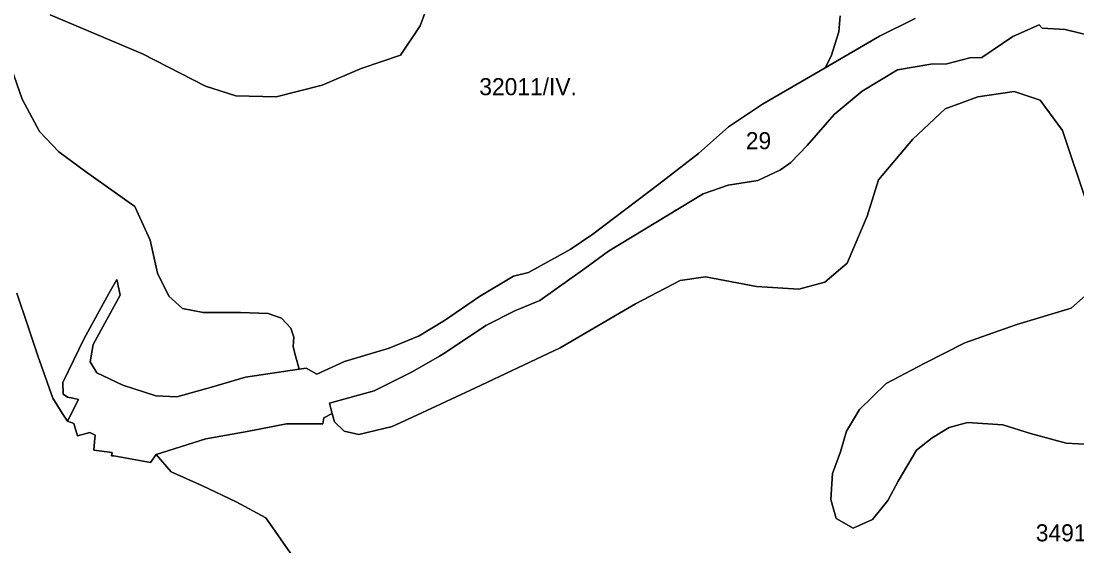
# Model space of a CAD drawing. Extents: x -521621 to -516761, y -1190184 to -1184927.
# Drawn here: x -518666 to -517738, y -1186934 to -1186473 of the extents above; entities that cross this region are included whole.
import ezdxf

# ---------------------------------------------------------------- set-up
doc = ezdxf.new("R2010")
doc.units = 0
doc.layers.add('BPEJ_s', color=7, linetype='Continuous')

msp = doc.modelspace()

# ---------------------------------------------------------------- linework, layer by layer
at = {"layer": 'BPEJ_s'}
for points in [[(-518640.68, -1186467.13), (-518559.44, -1186501.43), (-518504.22, -1186530.01), (-518477.56, -1186538.26), (-518442.01, -1186539.22), (-518401.39, -1186529.05), (-518367.11, -1186514.45), (-518332.52, -1186502.7), (-518315.38, -1186476.97), (-518305.23, -1186449.66)], [(-518305.23, -1186449.66), (-518315.38, -1186476.97), (-518332.52, -1186502.7), (-518367.11, -1186514.45), (-518401.39, -1186529.05), (-518442.01, -1186539.22), (-518477.56, -1186538.26), (-518504.22, -1186530.01), (-518559.44, -1186501.43), (-518640.68, -1186467.13)], [(-517945.65, -1186468.08), (-517946.92, -1186482.05), (-517953.58, -1186503.65), (-517958.84, -1186513.72), (-518014.04, -1186545.82), (-518044.12, -1186565.67), (-518070.38, -1186589.16), (-518105.19, -1186616.07), (-518163.5, -1186659.99), (-518183.31, -1186673.59), (-518220.01, -1186693.57), (-518233.13, -1186696.95), (-518262.99, -1186714.7), (-518293.79, -1186735.96), (-518316.22, -1186749.43), (-518342.54, -1186760.21), (-518381.71, -1186771.88), (-518406.33, -1186783.1), (-518415.68, -1186777.9), (-518421.78, -1186778.73), (-518425.83, -1186763.8), (-518427.02, -1186758.62), (-518426.5, -1186750.66), (-518429.2, -1186742.53), (-518437.32, -1186733.96), (-518449.05, -1186729.9), (-518473.4, -1186728.99), (-518506.33, -1186728.99), (-518524.37, -1186725.38), (-518536.54, -1186714.55), (-518546.47, -1186694.24), (-518552.78, -1186665.36), (-518566.31, -1186635.58), (-518609.61, -1186604.89), (-518633.07, -1186587.49), (-518650.2, -1186569.7), (-518665.44, -1186541.44), (-518677.5, -1186506.82)], [(-517879.79, -1186470.53), (-517911.12, -1186485.97), (-517958.84, -1186513.72), (-517953.58, -1186503.65), (-517946.92, -1186482.05), (-517945.65, -1186468.08)], [(-517720.36, -1186486.68), (-517747.87, -1186480.09), (-517768, -1186478.87), (-517770.79, -1186475.88), (-517793.73, -1186486.26), (-517821.06, -1186504.63), (-517831.83, -1186505.03), (-517851.97, -1186510.22), (-517865.93, -1186510.42), (-517895.2, -1186515.6), (-517926.37, -1186534.26), (-517951.06, -1186554.93), (-517974.73, -1186582.19), (-517989.16, -1186596.95), (-517998.24, -1186603.5), (-518018.2, -1186612.88), (-518044.36, -1186616.82), (-518066.39, -1186624.5), (-518149.53, -1186674.86), (-518170.5, -1186690.08), (-518209.87, -1186718.44), (-518231.94, -1186727.4), (-518257.59, -1186740.34), (-518292.98, -1186764.02), (-518298.35, -1186767.41), (-518322.21, -1186780.98), (-518355.75, -1186797.77), (-518394.91, -1186808.57), (-518393.36, -1186815.67), (-518392.84, -1186817.75), (-518400.1, -1186821.56), (-518400.97, -1186826.76), (-518432.75, -1186826.64), (-518467.55, -1186833.37), (-518503.82, -1186839.81), (-518547.6, -1186853.6), (-518552.44, -1186860.72), (-518584.71, -1186854.82), (-518586.88, -1186854.75), (-518586.36, -1186851.87), (-518602.52, -1186850.05), (-518601.71, -1186842.53), (-518601.12, -1186836.85), (-518606.01, -1186834.51), (-518616.73, -1186837.25), (-518620.06, -1186826.43), (-518625.42, -1186824.4), (-518615.73, -1186805.32), (-518620.98, -1186804.32), (-518625.56, -1186803.41), (-518629.47, -1186800.57), (-518629.72, -1186790.56), (-518610.91, -1186751.63), (-518589.12, -1186712.27), (-518582.06, -1186699.86), (-518579.29, -1186713.55), (-518603.01, -1186756.98), (-518605.57, -1186772.17), (-518599.8, -1186782.01), (-518576.96, -1186792.89), (-518547.69, -1186802.01), (-518529.34, -1186803.13), (-518498.81, -1186794.43), (-518468.84, -1186785.74), (-518421.78, -1186778.73), (-518415.68, -1186777.9), (-518406.33, -1186783.1), (-518381.71, -1186771.88), (-518342.54, -1186760.21), (-518316.22, -1186749.43), (-518293.79, -1186735.96), (-518262.99, -1186714.7), (-518233.13, -1186696.95), (-518220.01, -1186693.57), (-518183.31, -1186673.59), (-518163.5, -1186659.99), (-518105.19, -1186616.07), (-518070.38, -1186589.16), (-518044.12, -1186565.67), (-518014.04, -1186545.82), (-517958.84, -1186513.72), (-517911.12, -1186485.97), (-517879.79, -1186470.53)], [(-517728.74, -1186632.84), (-517750.05, -1186568.88), (-517769.83, -1186542.23), (-517792.66, -1186534.61), (-517824.62, -1186539.18), (-517853.54, -1186549.84), (-517881.7, -1186576.49), (-517912.13, -1186612.28), (-517922.03, -1186644.26), (-517939.53, -1186685.38), (-517959.31, -1186702.13), (-517982.14, -1186708.22), (-518019.43, -1186705.94), (-518064.33, -1186697.56), (-518086.39, -1186700.61), (-518125.97, -1186721.17), (-518192.17, -1186760), (-518266.74, -1186795.02), (-518318.31, -1186819.19), (-518340.01, -1186829.15), (-518369.28, -1186836.12), (-518382.23, -1186833.13), (-518390.59, -1186824.97), (-518392.84, -1186817.75), (-518393.36, -1186815.67), (-518394.91, -1186808.57), (-518355.75, -1186797.77), (-518322.21, -1186780.98), (-518298.35, -1186767.41), (-518292.98, -1186764.02), (-518257.59, -1186740.34), (-518231.94, -1186727.4), (-518209.87, -1186718.44), (-518170.5, -1186690.08), (-518149.53, -1186674.86), (-518066.39, -1186624.5), (-518044.36, -1186616.82), (-518018.2, -1186612.88), (-517998.24, -1186603.5), (-517989.16, -1186596.95), (-517974.73, -1186582.19), (-517951.06, -1186554.93), (-517926.37, -1186534.26), (-517895.2, -1186515.6), (-517865.93, -1186510.42), (-517851.97, -1186510.22), (-517831.83, -1186505.03), (-517821.06, -1186504.63), (-517793.73, -1186486.26), (-517770.79, -1186475.88), (-517768, -1186478.87), (-517747.87, -1186480.09), (-517720.36, -1186486.68)], [(-518677.5, -1186506.82), (-518665.44, -1186541.44), (-518650.2, -1186569.7), (-518633.07, -1186587.49), (-518609.61, -1186604.89), (-518566.31, -1186635.58), (-518552.78, -1186665.36), (-518546.47, -1186694.24), (-518536.54, -1186714.55), (-518524.37, -1186725.38), (-518506.33, -1186728.99), (-518473.4, -1186728.99), (-518449.05, -1186729.9), (-518437.32, -1186733.96), (-518429.2, -1186742.53), (-518426.5, -1186750.66), (-518427.02, -1186758.62), (-518425.83, -1186763.8), (-518421.78, -1186778.73), (-518468.84, -1186785.74), (-518498.81, -1186794.43), (-518529.34, -1186803.13), (-518547.69, -1186802.01), (-518576.96, -1186792.89), (-518599.8, -1186782.01), (-518605.57, -1186772.17), (-518603.01, -1186756.98), (-518579.29, -1186713.55), (-518582.06, -1186699.86), (-518589.12, -1186712.27), (-518610.91, -1186751.63), (-518629.72, -1186790.56), (-518629.47, -1186800.57), (-518625.56, -1186803.41), (-518620.98, -1186804.32), (-518615.73, -1186805.32), (-518625.42, -1186824.4), (-518630.19, -1186817.27), (-518638.37, -1186804.29), (-518651.63, -1186767.02), (-518660.38, -1186740.48), (-518670.25, -1186711.96)], [(-518429.42, -1186940.33), (-518450.92, -1186909.41), (-518477.12, -1186895.29), (-518506.69, -1186881.17), (-518534.23, -1186869.07), (-518547.6, -1186853.6), (-518503.82, -1186839.81), (-518467.55, -1186833.37), (-518432.75, -1186826.64), (-518400.97, -1186826.76), (-518400.1, -1186821.56), (-518392.84, -1186817.75), (-518390.59, -1186824.97), (-518382.23, -1186833.13), (-518369.28, -1186836.12), (-518340.01, -1186829.15), (-518318.31, -1186819.19), (-518266.74, -1186795.02), (-518192.17, -1186760), (-518125.97, -1186721.17), (-518086.39, -1186700.61), (-518064.33, -1186697.56), (-518019.43, -1186705.94), (-517982.14, -1186708.22), (-517959.31, -1186702.13), (-517939.53, -1186685.38), (-517922.03, -1186644.26), (-517912.13, -1186612.28), (-517881.7, -1186576.49), (-517853.54, -1186549.84), (-517824.62, -1186539.18), (-517792.66, -1186534.61), (-517769.83, -1186542.23), (-517750.05, -1186568.88), (-517728.74, -1186632.84)], [(-517703.63, -1186846.04), (-517747.01, -1186843.76), (-517778.2, -1186835.38), (-517802.56, -1186827.77), (-517833.76, -1186825.48), (-517849.74, -1186830.05), (-517864.95, -1186839.19), (-517878.65, -1186849.85), (-517894.63, -1186877.26), (-517903.76, -1186894.01), (-517917.46, -1186910.76), (-517934.2, -1186918.37), (-517949.42, -1186910), (-517953.99, -1186893.25), (-517952.47, -1186870.4), (-517945.62, -1186851.37), (-517940.29, -1186833.09), (-517928.88, -1186814.06), (-517905.29, -1186791.22), (-517871.8, -1186773.7), (-517836.04, -1186755.43), (-517790.38, -1186739.44), (-517742.44, -1186724.97), (-517722.65, -1186707.46)], [(-517722.65, -1186707.46), (-517742.44, -1186724.97), (-517790.38, -1186739.44), (-517836.04, -1186755.43), (-517871.8, -1186773.7), (-517905.29, -1186791.22), (-517928.88, -1186814.06), (-517940.29, -1186833.09), (-517945.62, -1186851.37), (-517952.47, -1186870.4), (-517953.99, -1186893.25), (-517949.42, -1186910), (-517934.2, -1186918.37), (-517917.46, -1186910.76), (-517903.76, -1186894.01), (-517894.63, -1186877.26), (-517878.65, -1186849.85), (-517864.95, -1186839.19), (-517849.74, -1186830.05), (-517833.76, -1186825.48), (-517802.56, -1186827.77), (-517778.2, -1186835.38), (-517747.01, -1186843.76), (-517703.63, -1186846.04)], [(-518670.25, -1186711.96), (-518660.38, -1186740.48), (-518651.63, -1186767.02), (-518638.37, -1186804.29), (-518630.19, -1186817.27), (-518625.42, -1186824.4), (-518620.06, -1186826.43), (-518616.73, -1186837.25), (-518606.01, -1186834.51), (-518601.12, -1186836.85), (-518601.71, -1186842.53), (-518602.52, -1186850.05), (-518586.36, -1186851.87), (-518586.88, -1186854.75), (-518584.71, -1186854.82), (-518552.44, -1186860.72), (-518547.6, -1186853.6), (-518534.23, -1186869.07), (-518506.69, -1186881.17), (-518477.12, -1186895.29), (-518450.92, -1186909.41), (-518429.42, -1186940.33)]]:
    msp.add_lwpolyline(points, dxfattribs=at)

# ---------------------------------------------------------------- texts
for s, p in [('32011/IV.', (-518263.26, -1186537.84)), ('29', (-518028.76, -1186585.32)), ('34911/IV.', (-517773.65, -1186930.07))]:
    msp.add_text(s, height=15, dxfattribs=at).set_placement(p)

doc.saveas('drawing.dxf')
